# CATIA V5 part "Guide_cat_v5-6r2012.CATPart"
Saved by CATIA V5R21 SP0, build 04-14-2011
Part number: Guide
Bounding box of the stored display mesh (mm): x -25 to 25, y -50 to 25, z -10 to 10
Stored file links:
  D:\CATIA V5R21 E-RESOURCES\CATIA-V5R21\catia-v5r21-Tut\c16-catia-v5r21-tut\c16-catia-v5r21-tut05\Guide_cat_v5r21.CATPart
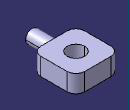
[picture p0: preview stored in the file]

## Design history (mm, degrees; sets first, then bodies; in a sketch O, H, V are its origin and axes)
Body1 (main body)
  Sketch1 on xy-plane, origin (0, 0, 0), H (1, 0, 0), V (0, 1, 0)
    circle A1 centre (0, 0) radius 10
    line L1 (-25, 25) -> (25, 25)
    line L2 (25, 25) -> (25, -25)
    line L3 (25, -25) -> (-25, -25)
    line L4 (-25, -25) -> (-25, 25)
    radius A1 = 10
    length L4 = 50
    length L3 = 50
    distance V L4 = 25
    distance L3 H = 25
    horizontal: L1 H, L3 H
    vertical: L2 V, L4 V
  Pad1: profile Sketch1, direction (0, 0, 1), length 10, mirrored extent
  Sketch2 on face of Pad1 from Sketch1.L3, origin (0, -25, 0), H (1, 0, 0), V (0, 0, 1)
    circle A1 centre (0, 0) radius 7.5
    point P1 (0, 0)
    reference projected line E1 (-25, 10) -> (25, 10) from edge [face of Pad1 from Sketch1.L3 | end face of Pad1]
    radius A1 = 7.5
    distance E1 P1 = 10
    coincidence: P1 V
  Pad2: profile Sketch2, direction (0, -1, 0), length 25
  Fillet1: radius 10, on edge [face of Pad1 from Sketch1.L2 | face of Pad1 from Sketch1.L3]; edge [face of Pad1 from Sketch1.L3 | face of Pad1 from Sketch1.L4]; edge [face of Pad1 from Sketch1.L1 | face of Pad1 from Sketch1.L2]; edge [face of Pad1 from Sketch1.L4 | face of Pad1 from Sketch1.L1]
  Fillet2: radius 2, on edge [face of Pad1 from Sketch1.L3 | face of Pad2 from Sketch2.A1]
